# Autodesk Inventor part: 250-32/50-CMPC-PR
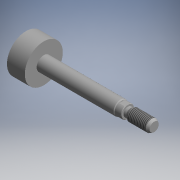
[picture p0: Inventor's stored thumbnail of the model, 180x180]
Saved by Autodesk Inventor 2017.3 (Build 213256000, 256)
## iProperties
Part Number: 250-32/50-CMPC-PR
Material: Generic
Catalog Web Link: www.cadenas.de
Description: CMPC-PR-
Vendor: METALWORK
Document SubType Name: Modeling
Designer: partserver
Manufacturer: METALWORK
Mass: 21.5325 g
Surface Area: 64.2527 cm^2
Volume: 21.5325 cm^3
Density: 1 g/cm^3
Appearance: PSOLRGB-192-192-192
Category: PARTsolutions
Company: METALWORK
Title: 250-32/50-CMPC-PR
Author: Cadenas PARTsolutions
PSOL_IDENT_0: {$CADENAS_DATA\23d-libs\metalwork\actuators\comp_cyl_ser_cmpc\parts\cmpc_piston_rod.prj},194 {VTYP=3
PSOL_IDENT_1: D},{NB=250-32/50-CMPC-PR},{LINA=250-32/50-CMPC-PR},{NN=CMPC-PR},{DATE=18.06.2021 08:06:07},{GEOMDATE=
PSOL_IDENT_2: 27.05.2020 09:13:00},{VERSION=},{LINEID=50},{WBVAR=TYPE,VE,HUB},{WBNUMERIC=TYPE,HUB}  {NB=250-32/50-
PSOL_IDENT_3: CMPC-PR},{LINA=250-32/50-CMPC-PR},{KT=DUMMY},{IDNR=},{TYPE=25},{TX= 23,'UNITOP male', 24,'UNITOP fem
PSOL_IDENT_4: ale', 25,'ISO male', 26,'ISO female' },{VE=0},{VX='0','Double-acting','1','Double-acting, through-ro
PSOL_IDENT_5: d','2','Double-acting, perfored through-rod','3','Single-acting, retracted rod','4','Single-acting,
PSOL_IDENT_6: extended rod','5','Single acting, through-rod','6','Single-acting, perfored through-rod','A','Double
PSOL_IDENT_7: -acting, through-rod, non-rotating'},{HUB=50},{DI=32.000},{C=12.000},{CH=10.000},{G=44.500},{HH=14.7
PSOL_IDENT_8: 50},{M=14.000},{N=50.500},{P=6.000},{P1=0.000},{P2=2.500},{R=10.000},{RP=1.250},{S=22.000},{S1=6.000
PSOL_IDENT_9: },{CD=11.000},{CL=5.600},{CCH=0.500},{RCH=2.000},{PP=50.25}
NB: 250-32/50-CMPC-PR
NN: CMPC-PR
NBSYN: $TYPE.$VE.-$DI./$HUB.-CMPC-PR
LINA: 250-32/50-CMPC-PR
CATALOG: Metalwork
TYPE: ISO male
VE: Double-acting
HUB: 50
DI: 32
C: 12
CH: 10
G: 44.5
HH: 14.75
M: 14
N: 50.5
P: 6
P1: 0
P2: 2.5
R: 10
RP: 1.25
S: 22
S1: 6
CD: 11
CL: 5.6
CCH: 0.5
RCH: 2
SUPPLIER: METALWORK
ARTICLENO: 250-32/50-CMPC-PR
BOMINFO: 250-32/50-CMPC-PR
CREATOR: CADENAS GmbH
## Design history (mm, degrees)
sketch "Sketch_1"
  geometry: L1 (7.5, 0)-(-78.25, 0); L2 (-78.25, 0)-(-78.25, 6); L3 (-78.25, 6)-(-7.5, 6); L4 (-7.5, 6)-(-7.5, 16); L5 (-7.5, 16)-(7.5, 16); L6 (7.5, 16)-(7.5, 0); L7 (7.5, 0)-(-78.25, 0)
  constraints: 14 end point
revolve "Revolution1" sketch "Sketch_1" stored, may be unused: angle "d0" = 360 deg
sketch "Sketch_2"
  geometry: L1 (-78.25, 0)-(-133.85, 0); L2 (-133.85, 0)-(-133.85, 11); L3 (-133.85, 11)-(-67.15, 11); L4 (-67.15, 11)-(-72.65, 5.5); L5 (-72.65, 5.5)-(-77.75, 5.5); L6 (-77.75, 5.5)-(-78.25, 5.211); L7 (-78.25, 5.211)-(-78.25, 0); L8 (-78.25, 0)-(-133.85, 0)
  constraints: 16 end point
revolve "Revolution2" sketch "Sketch_2" stored, may be unused: angle "d1" = 360 deg
sketch "Sketch_3"
  geometry: L1 (-20, -10)-(20, -10); L2 (20, -10)-(20, 10); L3 (20, 10)-(-20, 10); L4 (-20, 10)-(-20, -10); L5 (-10, -5)-(10, -5); L6 (10, -5)-(10, 5); L7 (10, 5)-(-10, 5); L8 (-10, 5)-(-10, -5)
  constraints: 16 end point
extrude "Extrusion1" cut sketch "Sketch_3" distance "d2" = 5.04; taper "d3" = 0 deg
sketch "Sketch_5"
  geometry: L1 (-78.25, 0.112)-(-100.25, 0.112); L2 (-100.25, 0.112)-(-100.25, 3.957); L3 (-100.25, 3.957)-(-98.25, 5.112); L4 (-98.25, 5.112)-(-82.45, 5.112); L5 (-82.45, 5.112)-(-80.45, 3.957); L6 (-80.45, 3.957)-(-78.25, 3.957); L7 (-78.25, 3.957)-(-78.25, 0.112); L8 (-78.25, 0.112)-(-100.25, 0.112)
  constraints: 16 end point
revolve "Revolution3" sketch "Sketch_5" stored, may be unused: angle "d4" = 360 deg
thread "Thread1" dims "d5" = 15.8, "d6" = 0
node "rod_XY"
node "rod_YZ"
node "rod_ZX"
node "rod_X"
node "rod_Y"
node "rod_Z"
node "rod_Center"
node "rod_acc_l_XY"
node "rod_acc_l_YZ"
node "rod_acc_l_ZX"
node "rod_acc_l_X"
node "rod_acc_l_Y"
node "rod_acc_l_Z"
node "rod_acc_l_Center"
body "Solid1"
other parameters: "d7" = 0
